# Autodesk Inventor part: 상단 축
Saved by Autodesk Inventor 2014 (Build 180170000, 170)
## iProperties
Created: 2024-05
Part Number: 상단 축
Material: 일반
Document SubType Name: Modeling
Designer: dg
Density: 1 g/cm^3
Appearance: 기본값
Author: dg
Author: jhkim
Creation Date: 2024-05-07
Sending System: Autodesk Inventor 2025
Preprocessor: ST-DEVELOPER v20
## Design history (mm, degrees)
node "상단 축1"
node "솔리드1"
node "기준1"
